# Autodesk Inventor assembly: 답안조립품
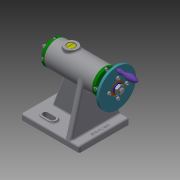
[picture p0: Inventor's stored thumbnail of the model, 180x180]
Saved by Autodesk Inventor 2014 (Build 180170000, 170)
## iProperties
Created: 2019-10
Part Number: 답안조립품
Document SubType Name: Assembly
Designer: kh
Author: kh
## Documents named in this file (18)
- C:\Users\kh\Desktop\491004V1033\답안조립품.iam
- C:\Users\kh\Desktop\491004V1033\본체.ipt
- C:\Users\kh\Desktop\491004V1033\나사.ipt
- C:\Users\kh\Desktop\491004V1033\나사축.ipt
- C:\Users\kh\Desktop\491004V1033\너트 M8.ipt
- C:\Users\kh\Desktop\491004V1033\돌림판.ipt
- C:\Users\kh\Desktop\491004V1033\멈춤나사 M3.ipt
- C:\Users\kh\Desktop\491004V1033\볼트 M3.ipt
- C:\Users\kh\Desktop\491004V1033\부시.ipt
- C:\Users\kh\Desktop\491004V1033\센터.ipt
- C:\Users\kh\Desktop\491004V1033\센터홀더.ipt
- C:\Users\kh\Desktop\491004V1033\슬리브.ipt
- C:\Users\kh\Desktop\491004V1033\와셔.ipt
- C:\Users\kh\Desktop\491004V1033\중공축.ipt
- C:\Users\kh\Desktop\491004V1033\커버.ipt
- C:\Users\kh\Desktop\491004V1033\키 4 x 4 x 10.ipt
- C:\Users\kh\Desktop\491004V1033\플랜지.ipt
- C:\Users\kh\Desktop\491004V1033\핸들.ipt
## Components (2 placed, 2 different names)
1. 플랜지:1 — Insert:8, Mate:6, Insert:11, Mate:8, Insert:19
2. 핸들:1 — Insert:12
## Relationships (6: Insert 4, Mate 2)
- Insert:8: 플랜지:1
- Mate:6: 플랜지:1
- Insert:11: 플랜지:1
- Mate:8: 플랜지:1
- Insert:12: 핸들:1
- Insert:19: 플랜지:1
